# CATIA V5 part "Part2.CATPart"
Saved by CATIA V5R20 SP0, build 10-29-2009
Part number: Part2
Bounding box of the stored display mesh (mm): x 3 to 22, y -7 to 63.99, z 108.003 to 121.997
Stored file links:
  E:\Ehsan\Amoozesh\CATIA\CATIA Course\Advanced\Exercises\DMU Kinematic\1\Part2.CATPart
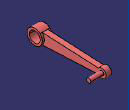
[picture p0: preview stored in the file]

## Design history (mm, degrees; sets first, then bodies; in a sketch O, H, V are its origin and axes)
Body1 (main body)
  DatumSurface1
  DatumCurve1
  Sketch1 on face of DatumSurface1, origin (5, 0, 0), H (0, 1, 0), V (0, 0, 1)
    projected circle E1 centre (0, 115) radius 5 from edge of DatumCurve1
    arc A1 centre (0, 115) radius 7 from (4.899, 120) to (4.899, 110) ccw
    point P1 (0, 115)
    circle A2 centre (60, 115) radius 2
    point P2 (60, 115)
    arc A3 centre (60, 115) radius 4 from (56.8775, 112.5) to (56.8775, 117.5) ccw
    line L1 (4.899, 120) -> (56.8775, 117.5)
    point P3 (4.899, 120)
    point P4 (56.8775, 117.5)
    axis line L2 (0, 115) -> (60, 115)
    point P5 (60, 115)
    point P6 (56.8775, 112.5)
    point P7 (4.899, 110)
    line L3 (4.899, 110) -> (56.8775, 112.5)
    arc A4 centre (60, 115) radius 4 from (56.8775, 117.5) to (56.8775, 112.5) ccw
    arc A5 centre (0, 115) radius 7 from (4.899, 110) to (4.899, 120) ccw
    radius A1 = 7
    radius A3 = 4
    distance P1 P2 = 60
    distance P3 P1 V = 5
    distance P4 P2 V = 2.5
    concentricity: P1 E1, P5 A2
    horizontal: L2 H
    symmetry: P4 P6 L2, P3 P7 L2, L1 L3 L2
    coincidence: A3 A4, A1 A5
  MultiPad1: profile Sketch1, domains (length 5; length 5; length 7 / length 2; length 17; length 0)
  Point1: type Center, Curve edge [face of MultiPad1 from Sketch1.A2 | face of MultiPad1]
